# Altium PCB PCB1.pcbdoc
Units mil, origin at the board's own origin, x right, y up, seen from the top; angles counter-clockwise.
Board outline 1785 x 1065 mil, 2 copper layers (Top Layer, Bottom Layer), stack 62.2 mil thick; 34 components, 19 nets, 86 pads, 3 vias.
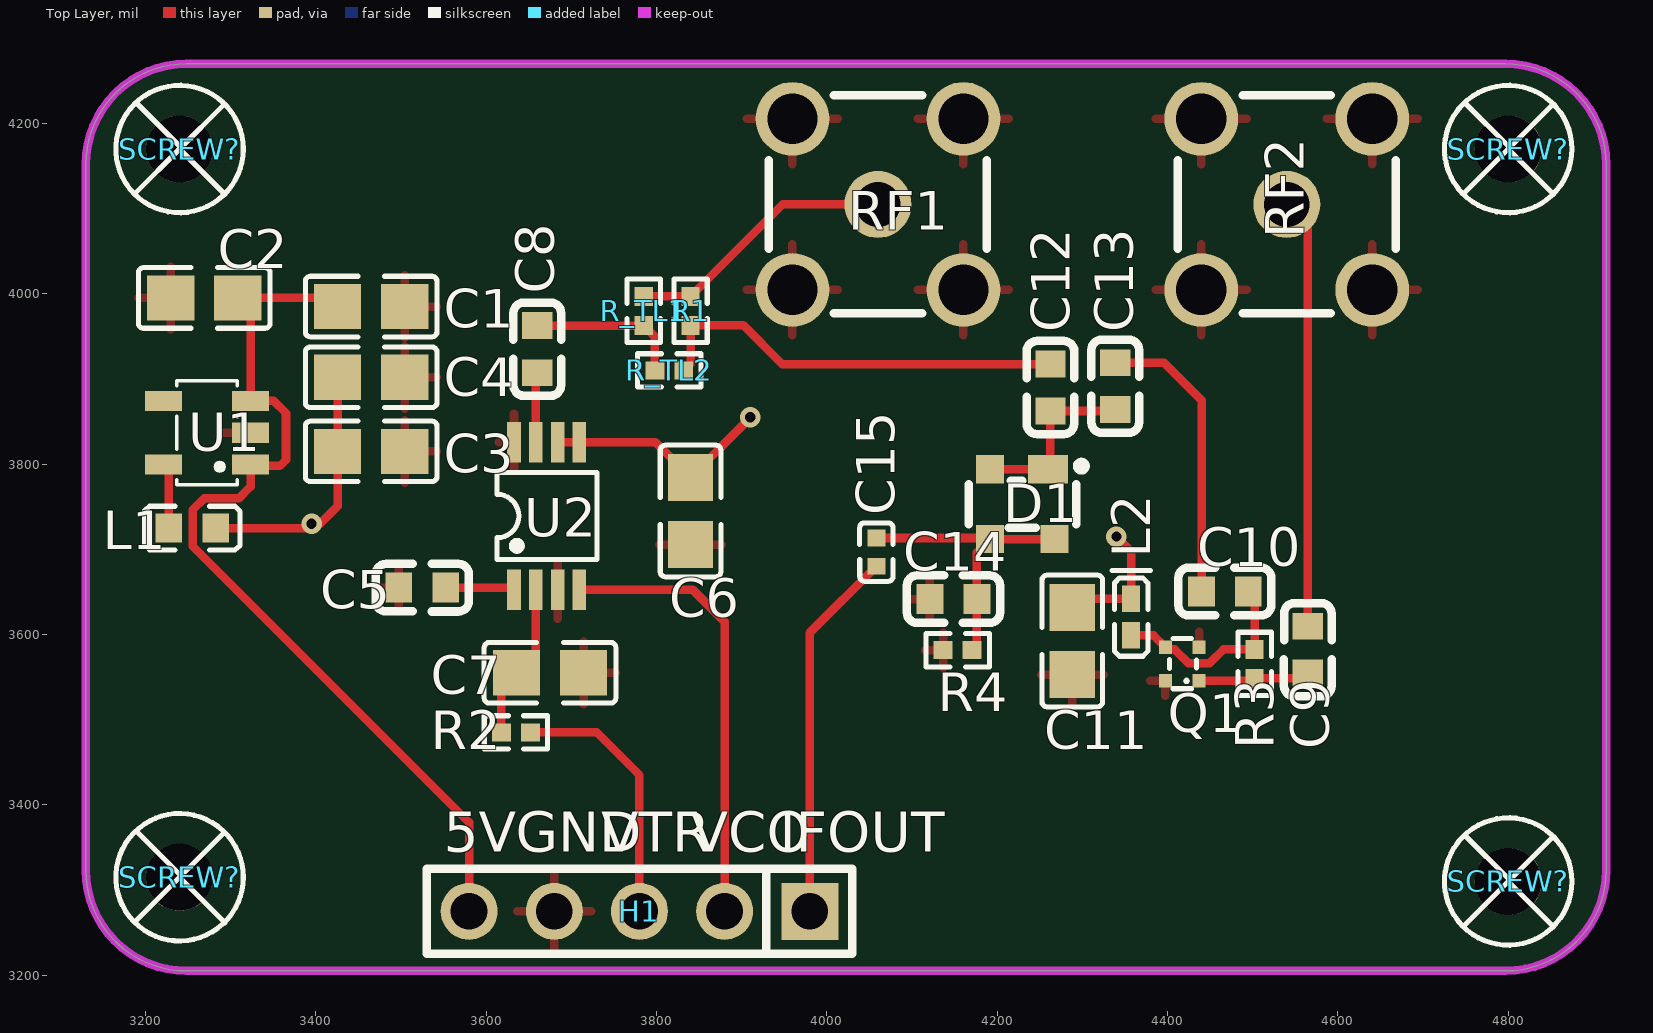
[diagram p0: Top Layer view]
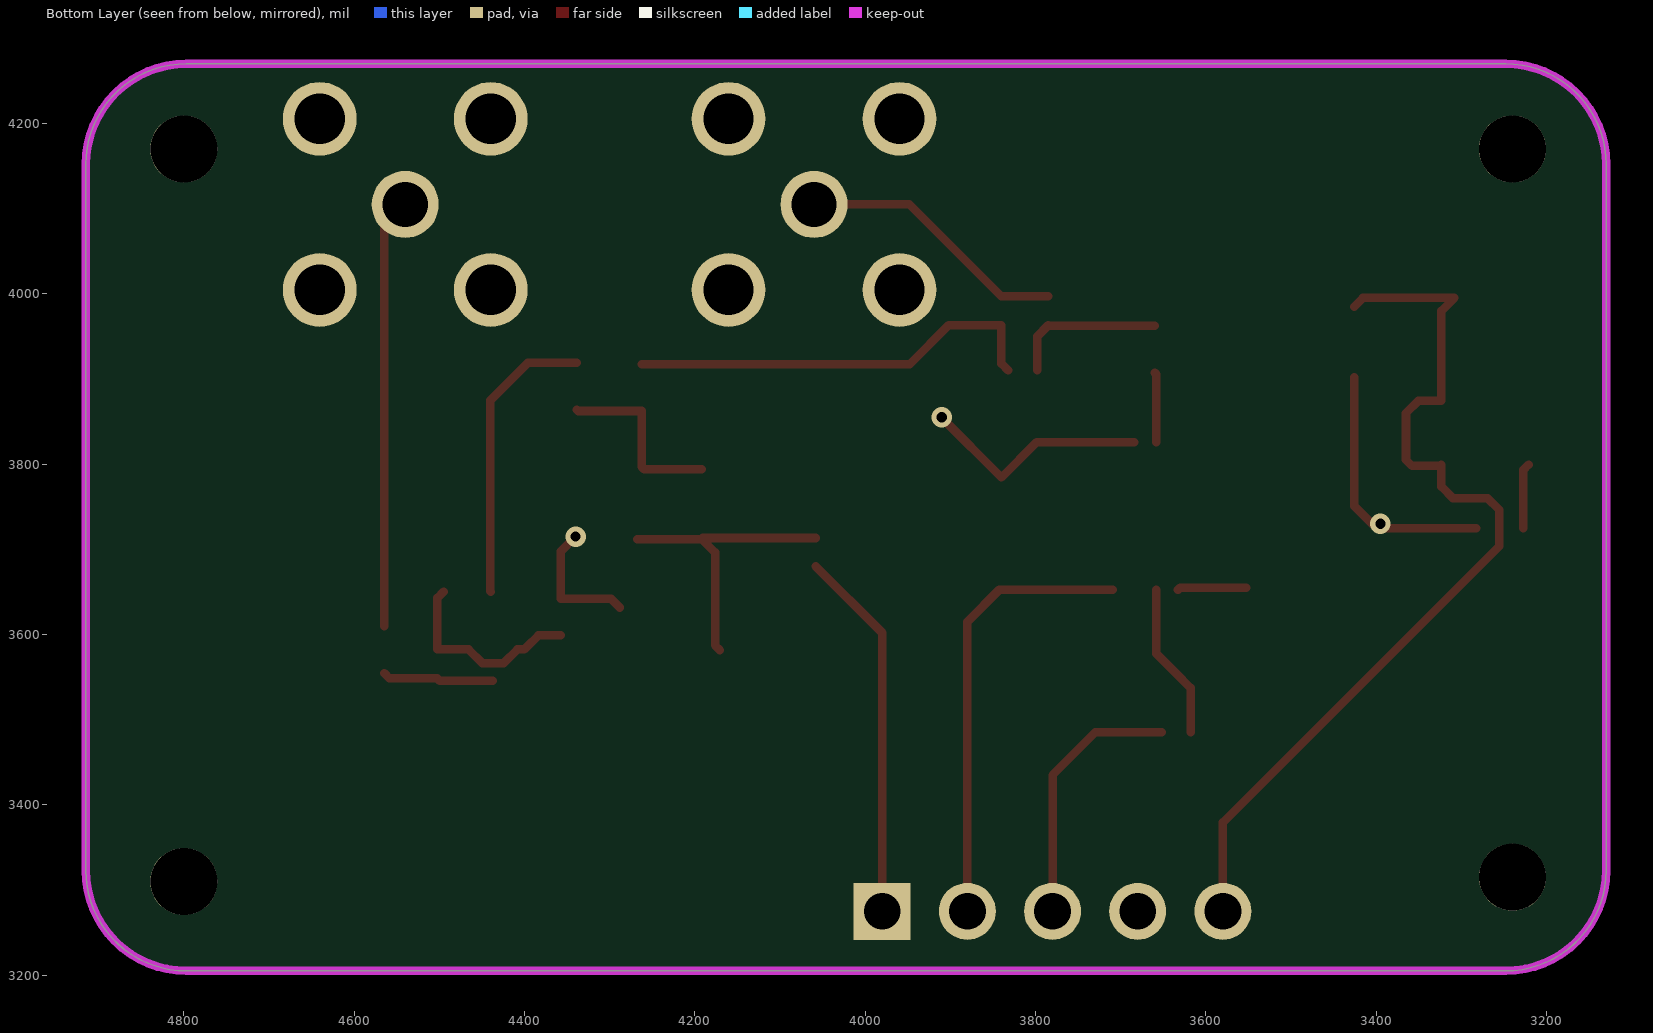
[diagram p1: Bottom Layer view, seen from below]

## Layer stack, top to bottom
Top Solder Mask Layer: solder mask 0.4, Dk 3.3
Top Layer: signal copper 1.4
Dielectric1: surface 59.4, FR4, Dk 4.5
Bottom Layer: signal copper 1.4
Bottom Solder Mask Layer: solder mask 0.4, Dk 3.3

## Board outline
3248.1,4270 ccw(c3248.1,4151.9) 3130,4151.9 3130,3323.1 ccw(c3248.1,3323.1) 3248.1,3205 4796.9,3205 ccw(c4796.9,3323.1) 4915,3323.1 4915,4151.9 ccw(c4796.9,4151.9) 4796.9,4270

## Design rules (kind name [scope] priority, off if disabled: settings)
BoardOutlineClearance copperThickness1oz [All] p0: genericclearance=10 ignorepadtopadclearanceinfootprint=FALSE except(0: Arc-SplitContinuation Track-SplitContinuation SMDPad-SplitContinuation THPad-SplitContinuation Via-SplitContinuation Fill-SplitContinuation Poly-SplitContinuation Region-SplitContinuation Text-SplitContinuation)
BoardOutlineClearance copperThickness2oz [All] p0: genericclearance=10 ignorepadtopadclearanceinfootprint=FALSE except(0: Arc-SplitContinuation Track-SplitContinuation SMDPad-SplitContinuation THPad-SplitContinuation Via-SplitContinuation Fill-SplitContinuation Poly-SplitContinuation Region-SplitContinuation Text-SplitContinuation)
BoardOutlineClearance otherClearance [All] p0: genericclearance=10 ignorepadtopadclearanceinfootprint=FALSE except(0: Arc-SplitContinuation Track-SplitContinuation SMDPad-SplitContinuation THPad-SplitContinuation Via-SplitContinuation Fill-SplitContinuation Poly-SplitContinuation Region-SplitContinuation Text-SplitContinuation)
Clearance copperThickness1oz [All] p1: gap=7 ignorepadtopadclearanceinfootprint=FALSE
Clearance copperThickness2oz [All] p1: gap=7 ignorepadtopadclearanceinfootprint=FALSE
Clearance otherClearance [All] p1: gap=7 ignorepadtopadclearanceinfootprint=FALSE
DiffPairsRouting differentialPair [All] p1: maxuncoupledlength=10 minlimit=6 maxlimit=Infinity mostfreqgap=6 toplayer_minwidth=5 toplayer_prefwidth=10 toplayer_maxwidth=100 bottomlayer_minwidth=5 bottomlayer_prefwidth=10 bottomlayer_maxwidth=100
PasteMaskExpansion pasteMaskExpansion [All] p1: expansion=0
PlaneConnect innerPlane [All] p1: planeconnectstyle=Relief reliefexpansion=20 reliefentries=4 reliefconductorwidth=10 reliefairgap=10
PolygonConnect copperRegion [All] p1: connectstyle=Relief reliefentries=4 reliefconductorwidth=10 polygonreliefangle="90 Angle" airgapwidth=10
RoutingVias viaSize [All] p1: viastyle="Through Hole" holewidth=12.0078 minholewidth=11.811 maxholewidth=248.0314 width=12.0078 minwidth=11.811 maxwidth=248.0314
SolderMaskExpansion solderMaskExpansion [IsVia] p1: useseparateexpansions=TRUE expansion=-1000 expansionbottom=-1000
SolderMaskExpansion solderMaskExpansion [All] p2: useseparateexpansions=TRUE expansion=2 expansionbottom=2
Width copperThickness1oz [All] p1: maxlimit=100 minlimit=5 preferedwidth=10
Width copperThickness2oz [All] p1: maxlimit=100 minlimit=8 preferedwidth=10

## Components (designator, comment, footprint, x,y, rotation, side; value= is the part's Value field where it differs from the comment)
C1 "10uF" C0805#1 3465,3985 r180 top
C2 "100nF" C0805#2 3269,3995.1 r180 top
C3 "10uF" C0805#1 3465,3815 r180 top
C4 "100pF" C0805#1 3465,3901.9 r180 top
C5 "220pF" C0603#1 3525,3655 r0 top
C6 "100nF" C0805#1 3840,3745 r270 top
C7 "100pF" C0805#1 3675,3555 r0 top
C8 "22pF" C0603#1 3660,3935 r90 top
C9 "22pF" C0603#2 4564.7,3582.1 r90 top
C10 "22pF" C0603#3 4467.3,3650.4 r0 top
C11 "100pF" C0805#3 4288.2,3592.3 r90 top
C12 "22pF" C0603#2 4262.5,3889.9 r90 top
C13 "22pF" C0603#3 4338.6,3891.6 r90 top
C14 "10pF" C0603#3 4148.6,3641.6 r180 top
C15 "1uF" C0402 4058.2,3696.7 r90 top
D1 "BAT15-099R" SOT-143-4_L2.9-W1.3-P1.92-LS2.3-BR 4229.6,3753 r90 top
H1 "PZ2.54-1x5-11.2" HDR-TH_5P-P2.54-V-M 3780,3275 r180 top
L1 "BLM18HE152SN1D" L0603 3255,3725 r0 top
L2 "10nH" L0402-RD 4357.3,3620.4 r270 top
Q1 "BFP840FESDH6327XTSA1" TSFP-4-1_L1.4-W0.8-P1.00-LS1.2-TL-1 4417.3,3565.4 r180 top
R1 "100Ω" R0402#1 3840,3980 r90 top
R2 "100Ω" R0402#1 3635,3485 r180 top
R3 "4.7kΩ" R0402#2 4502.3,3565.4 r90 top
R4 "1kΩ" R0402#2 4153.6,3581.6 r0 top
R_TL1 "0Ω" R0402#1 3785,3980 r90 top
R_TL2 "0Ω" R0402#1 3815,3910 r0 top
RF1 "SMA-KE-10" SMA-TH_BWSMA-KE-Z001 4060,4105 r0 top
RF2 "SMA-KE-10" SMA-TH_BWSMA-KE-Z001 4540,4105 r90 top
SCREW? "" Screw-Hole-M2 4800,4170 r0 top
SCREW? "" Screw-Hole-M2 4800,3310 r0 top
SCREW? "" Screw-Hole-M2 3240,3315 r0 top
SCREW? "" Screw-Hole-M2 3240,4170 r0 top
U1 "ADP151AUJZ-3.3-R7" SOT-23-5_L3.0-W1.7-P0.95-LS2.8-BR 3272.3,3836.9 r0 top
U2 "MAX2750EUA+T" MSOP-8_L3.0-W3.0-P0.65-LS4.9-BL-1 3671.1,3739.1 r0 top

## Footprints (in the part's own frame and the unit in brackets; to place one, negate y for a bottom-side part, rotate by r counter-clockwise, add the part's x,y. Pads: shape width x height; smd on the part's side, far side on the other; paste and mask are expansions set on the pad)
C0402 [mil]
  rect 19.7x21.3 smd: 1(-16.5,0) 2(16.6,0)
  silkscreen extent -34,-20 34,20
C0603#1 [mil]
  rect 31.5x35.4 smd: 1(-27.6,0) 2(27.6,0)
  silkscreen extent -55,-28 55,28
C0603#2 [mil]
  rect 31.5x35.4 smd: 1(-27.5,0) 2(27.6,0)
  silkscreen extent -55,-28 55,28
C0603#3 [mil]
  rect 31.5x35.4 smd: 1(-27.6,0) 2(27.5,0)
  silkscreen extent -55,-28 55,28
C0805#1 [mil]
  rect 55.5x53.1 smd paste-3937 mask+2: 1(-39.4,0) 2(39.4,0)
  silkscreen extent -77,-36 77,36
C0805#2 [mil]
  rect 55.5x53.1 smd paste-3937 mask+2: 1(-39.4,0) 2(39.3,0)
  silkscreen extent -77,-36 77,36
C0805#3 [mil]
  rect 55.5x53.1 smd paste-3937 mask+2: 1(-39.3,0) 2(39.4,0)
  silkscreen extent -77,-36 77,36
HDR-TH_5P-P2.54-V-M [mil]
  rect 66.9x66.9 hole 43.3: 1(-200,0)
  round 66.9 hole 43.3: 2(-100,0) 3(0,0) 4(100,0) 5(200,0)
  silkscreen extent -250,-50 250,50
L0402-RD [mil]
  rect 31.1x21.3 smd paste-3937 mask+2: 1(-21.5,0) 2(21.4,0)
  silkscreen extent -55,-23 46,22
L0603 [mil]
  rect 31.5x34 smd paste-3937 mask+2: 1(-27.6,0) 2(27.6,0)
  silkscreen extent -56,-26 56,26
MSOP-8_L3.0-W3.0-P0.65-LS4.9-BL-1 [mil]
  rect 16x47.2 smd: 1(-38.4,-86.6) 2(-12.8,-86.6) 3(12.8,-86.6) 4(38.3,-86.6) 5(38.3,86.6) 6(12.8,86.6) 7(-12.8,86.6) 8(-38.4,86.6)
  silkscreen extent -58,-51 59,51
R0402#1 [mil]
  rect 22.3x21.3 smd paste-3937 mask+2: 1(-17,0) 2(17,0)
  silkscreen extent -37,-20 37,20
R0402#2 [mil]
  rect 22.3x21.3 smd paste-3937 mask+2: 1(-17,0) 2(17.1,0)
  silkscreen extent -37,-20 37,20
Screw-Hole-M2 [mil]
  round 78.7 hole 78.7: 1(0,0)
  silkscreen extent -75,-75 75,75
SMA-TH_BWSMA-KE-Z001 [mil]
  round 86.6 hole 59.1: 1(-100.4,-100.4) 2(-100.4,100.4) 3(100.4,100.4) 4(100.4,-100.4)
  round 78.7 hole 53.1: 5(0,0)
  silkscreen extent -128,-128 128,128
SOT-23-5_L3.0-W1.7-P0.95-LS2.8-BR [mil]
  rect 43.3x23.6 smd: 1(51.2,-37.4) 2(51.2,0) 3(51.2,37.4) 4(-51.2,37.4) 5(-51.2,-37.4)
  silkscreen extent -35,-61 35,61
SOT-143-4_L2.9-W1.3-P1.92-LS2.3-BR [mil]
  rect 33x47.2 smd: 1(41,-29.9)
  rect 33x33 smd: 2(41,37.8) 3(-41,37.8) 4(-41,-37.8)
  silkscreen extent -28,-74 50,63
TSFP-4-1_L1.4-W0.8-P1.00-LS1.2-TL-1 [mil]
  rect 15.7x15.7 smd paste+0 mask+2: 1(-19.7,19.6) 2(-19.7,-19.7) 3(19.7,-19.7) 4(19.7,19.6)
  silkscreen extent -17,-30 15,29

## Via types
v1: diameter 24, hole 12, Top Layer to Bottom Layer, 3 vias

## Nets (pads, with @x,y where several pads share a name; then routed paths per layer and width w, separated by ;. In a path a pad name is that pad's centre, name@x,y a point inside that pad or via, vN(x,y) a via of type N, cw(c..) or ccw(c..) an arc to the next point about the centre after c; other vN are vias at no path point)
3.3V: C3.2 C4.2 C6.1 C11.2 L1.2 L2.1 U2.5 U2.6 | length 731.3
  Top Layer w10: L1.2 3390,3725 v1(3395,3730) 3405,3730 3425.6,3750.6 C3.2 C4.2 ; U2.6 U2.5 3798.7,3825.7 C6.1 3910,3854.4 v1(3910,3855) ; C11.2 4298.4,3641.9 L2.1 4357.3,3697.7 v1(4340,3715)
$1N7: L1.1 U1.5 | length 77.1
  Top Layer w10: U1.5 3227.4,3793.2 L1.1
$1N12: C7.1 R2.2 U2.2 | length 184.2
  Top Layer w10: R2.2 3618,3537.3 C7.1 3658.3,3577.6 U2.2
$1N18: C8.1 U2.7 | length 82.4
  Top Layer w10: U2.7 3658.3,3905.7 C8.1
$1N20: C5.2 U2.1 | length 81.1
  Top Layer w10: C5.2 3630.1,3655 U2.1
$1N39: C9.1 Q1.1 R3.1 | length 131.3
  Top Layer w10: Q1.1 4499.6,3545.8 R3.1 4558.5,3548.4 C9.1
$1N41: C10.2 L2.2 Q1.3 R3.2 | length 236.3
  Top Layer w10: L2.2 4383.7,3599 Q1.3 4400.2,3582.5 4408.3,3582.5 4424.5,3566.3 4449.4,3566.3 4465.6,3582.5 R3.2 4502.3,3643 C10.2
$1N52: C12.1 C13.1 D1.1 D1.2 | length 214.1
  Top Layer w10: D1.2 D1.1 4262.5,3797 C12.1 4337,3862.4 C13.1
$1N56: C14.1 C15.2 D1.3 D1.4 R4.2 | length 348.9
  Top Layer w10: C15.2 4190.5,3713.3 D1.3 ; R4.2 4176.2,3587.1 C14.1 4176.2,3696.4 D1.3 ; D1.4 D1.3
+5V: C1.2 C2.1 H1.5 U1.1 U1.3 | length 1106.6
  Top Layer w10: C1.2 3415.5,3995.1 C2.1 3323.5,3980 U1.3 3350.7,3874.3 3365,3860 3365,3805 3357.9,3797.9 3325.1,3797.9 U1.1 3323.5,3773.6 3309.9,3760 3269.3,3760 3255.8,3746.6 3255.8,3703.4 3580,3379.3 H1.5
GND: C1.1 C2.2 C3.1 C4.1 C5.1 C6.2 C7.2 C11.1 C14.2 H1.4 Q1.2 Q1.4 R4.1 RF1.1 RF1.2 RF1.3 RF1.4 RF2.1 RF2.2 RF2.3 RF2.4 U1.2 U2.3 U2.8
IF_OUT_RAW: C15.1 H1.1 | length 437.6
  Top Layer w10: H1.1 3980,3602 C15.1
RF_LO_MIXER: C12.2 R1.1 R_TL2.2 | length 497.7
  Top Layer w10: R_TL2.2 3840,3918 R1.1 3902,3963 3947.5,3917.5 C12.2
RF_RX_AMP: C10.1 C13.2 | length 344.4
  Top Layer w10: C13.2 4395.9,3919.1 4440,3875 4440,3650.7 C10.1
RF_RX_IN: C9.2 RF2.5 | length 505.5
  Top Layer w10: RF2.5 4564.7,4080.3 C9.2
RF_TO_ANT: R1.2 R_TL1.2 RF1.5 | length 319.7
  Top Layer w10: R_TL1.2 R1.2 3948,4105 RF1.5
RF_TX_OUT: C8.2 R_TL1.1 R_TL2.1 | length 183.6
  Top Layer w10: C8.2 3784.6,3962.6 R_TL1.1 3798,3950 R_TL2.1
V_TUNE_RAMP: H1.3 R2.1 | length 308.7
  Top Layer w10: R2.1 3730,3485 3780,3435 H1.3
VCO_EN: H1.2 U2.4 | length 526.1
  Top Layer w10: U2.4 3842.5,3652.5 3880,3615 H1.2
pads on no net: SCREW?.1 U1.4

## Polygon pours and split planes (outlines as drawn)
GND on Top Layer (solid, remove dead copper, pour order 0): 3020,4315 3020,3175 5335,3175 5335,4315
3.3V on Bottom Layer (solid, remove dead copper, pour order 2): 3000,4405 3000,3000 5430,3000 5430,4405

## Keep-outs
Board Outline Layer:
  lines w10: 3130,4151.9 cw(c3248.1,4151.9) 3248.1,4270 4796.9,4270 ; 3130,4151.9 3130,4151.9 ; 3130,4151.9 3130,3323.1 ccw(c3248.1,3323.1) 3248.1,3205 4796.9,3205 ; 4796.9,3205 4796.9,3205 ; 4796.9,3205 ccw(c4796.9,3323.1) 4915,3323.1 4915,4151.9 ; 4796.9,4270 cw(c4796.9,4151.9) 4915,4151.9 ; 4796.9,4270 4796.9,4270 ; 4915,4151.9 4915,4151.9

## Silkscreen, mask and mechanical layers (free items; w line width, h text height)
Top Silkscreen Layer:
  text "5V" at 3550,3345 h47.2
  text "GND" at 3635,3345 h47.2
  text "VTR" at 3735,3345 h47.2
  text "VCO" at 3840,3345 h47.2
  text "IFOUT" at 3945,3345 h47.2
